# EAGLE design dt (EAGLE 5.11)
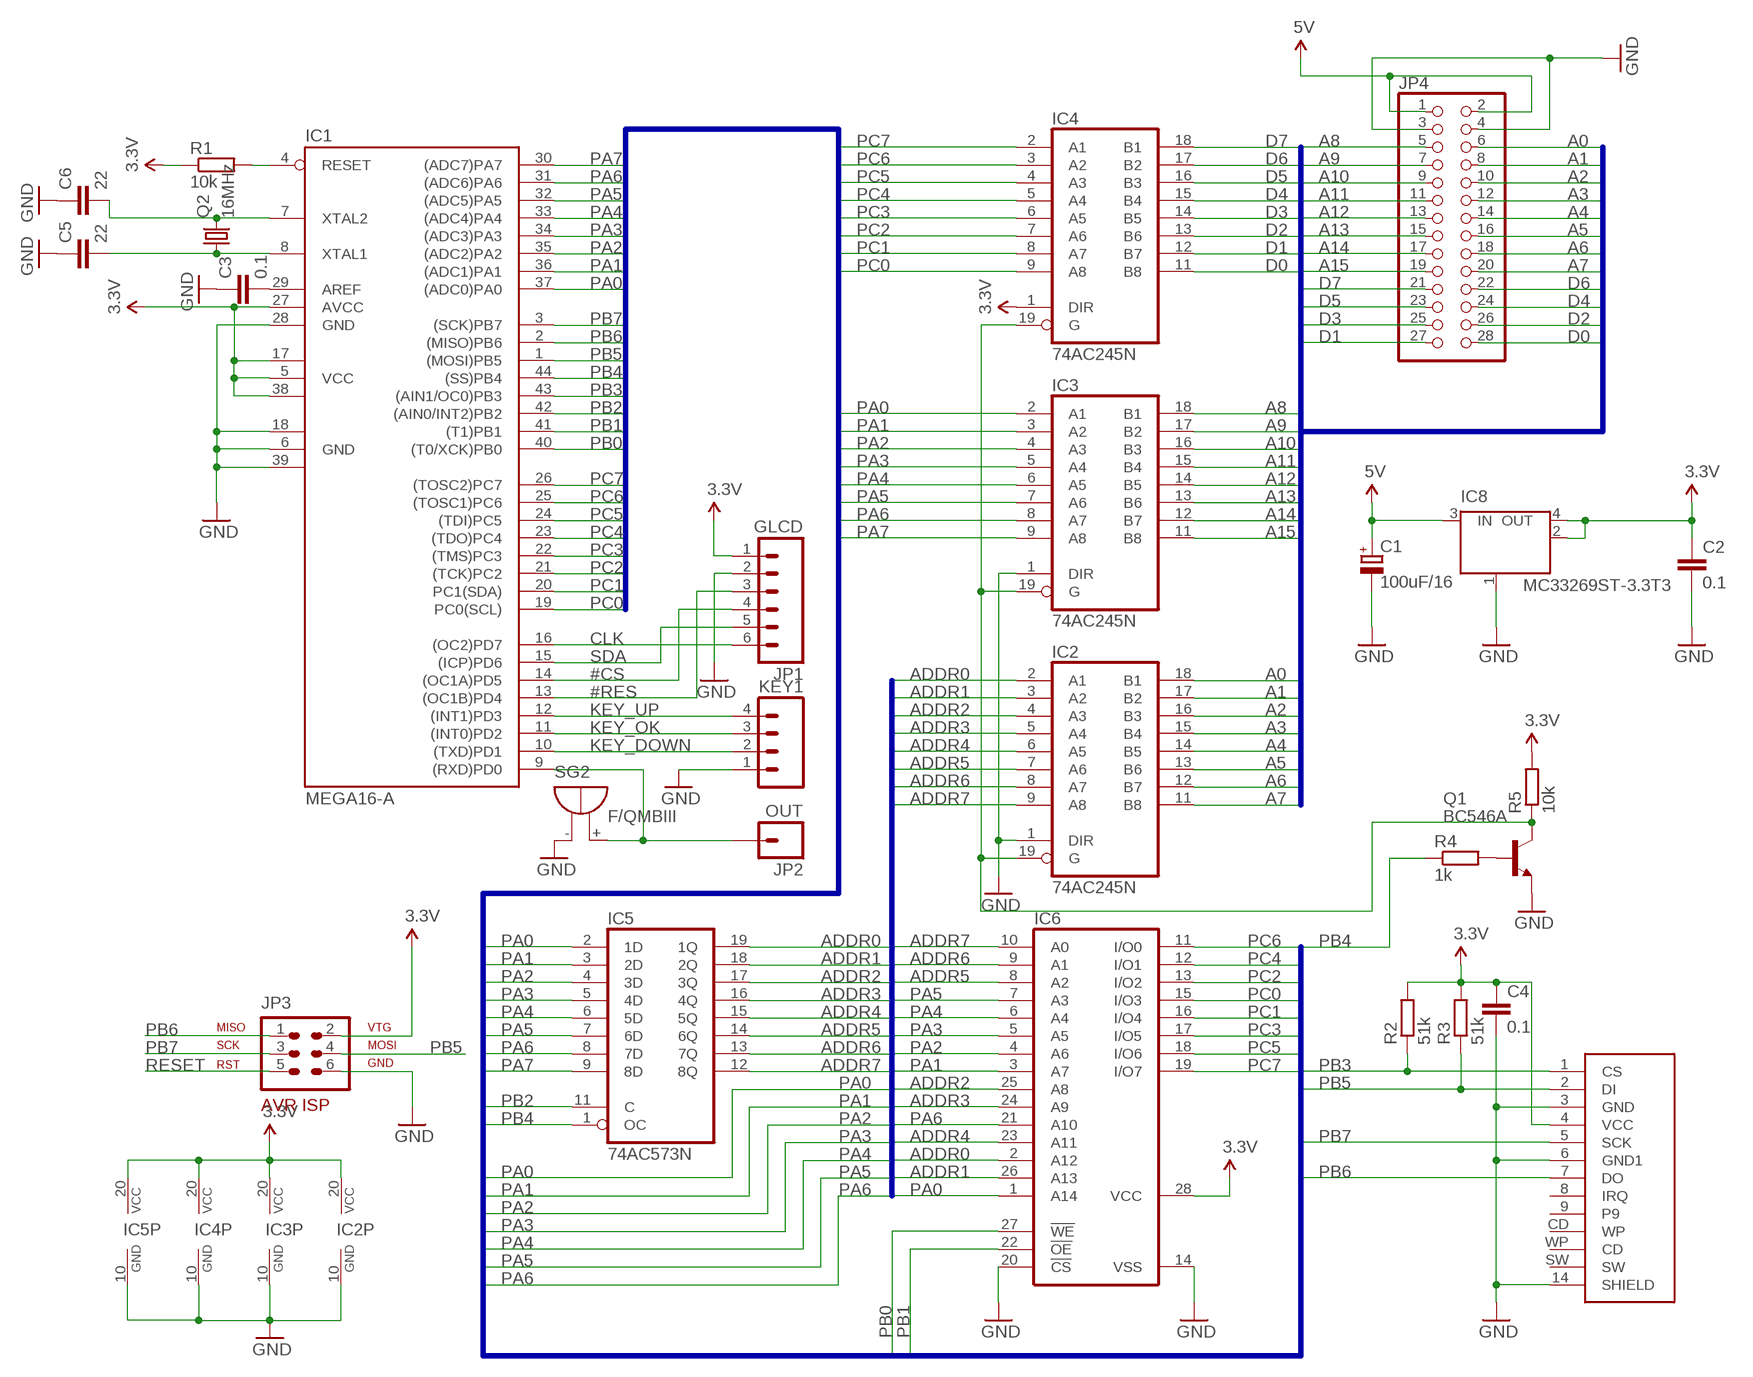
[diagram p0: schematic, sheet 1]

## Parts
C1  100uF/16  CPOL-EUE2,5-6E  [E2,5-6E]
C2  0.1  C-EU050-025X075  [C050-025X075]
C3  0.1  C-EU050-025X075  [C050-025X075]
C4  0.1  C-EU050-025X075  [C050-025X075]
C5  22  C-EU050-025X075  [C050-025X075]
C6  22  C-EU050-025X075  [C050-025X075]
IC1  MEGA16-A  [TQFP44]
IC2  74AC245N  [DIL20]
IC3  74AC245N  [DIL20]
IC4  74AC245N  [DIL20]
IC5  74AC573N  [DIL20]
IC6  62832P  [DIL28-3]
IC8  MC33269ST-3.3T3  [SOT223]
JP1  GLCD  M06POLAR  [MOLEX-1X6]
JP2  OUT  M01OFFSET  [1X01_OFFSET]
JP3  AVR-ISP-6  [AVR-ISP-6]
JP4  PINHD-2X14  [2X14]
KEY1  M04POLAR  [MOLEX-1X4]
Q1  BC546A  [TO92-EBC]
Q2  16MHz  CRYSTALHC49UP  [HC49UP]
R1  10k  R-EU_0207/10  [0207/10]
R2  51k  R-EU_0207/10  [0207/10]
R3  51k  R-EU_0207/10  [0207/10]
R4  1k  R-EU_0207/10  [0207/10]
R5  10k  R-EU_0207/10  [0207/10]
SG2  F/QMBIII  [F/QMBIII]
U$4  SD_CARD_SOCKETSD  [SD-MMC_SOCKET-PP]

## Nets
3.3V: C2.1 C4.1 IC1.5(VCC) IC1.17(VCC1) IC1.27(AVCC) IC1.38(VCC2) IC2.20(VCC) IC3.20(VCC) IC4.1(DIR) IC4.20(VCC) IC5.20(VCC) IC6.28(VCC) IC8.2(OUT) IC8.4(OUT) JP1.1 JP3.2 R1.1 R2.2 R3.2 R5.2 U$4.4(VCC)
5V: C1.+ IC8.3(IN) JP4.1 JP4.2
#CS: IC1.14((OC1A)PD5) JP1.4
#RES: IC1.13((OC1B)PD4) JP1.3
A0: IC2.18(B1) JP4.6
A1: IC2.17(B2) JP4.8
A2: IC2.16(B3) JP4.10
A3: IC2.15(B4) JP4.12
A4: IC2.14(B5) JP4.14
A5: IC2.13(B6) JP4.16
A6: IC2.12(B7) JP4.18
A7: IC2.11(B8) JP4.20
A8: IC3.18(B1) JP4.5
A9: IC3.17(B2) JP4.7
A10: IC3.16(B3) JP4.9
A11: IC3.15(B4) JP4.11
A12: IC3.14(B5) JP4.13
A13: IC3.13(B6) JP4.15
A14: IC3.12(B7) JP4.17
A15: IC3.11(B8) JP4.19
ADDR0: IC2.2(A1) IC5.19(1Q) IC6.2(A12)
ADDR1: IC2.3(A2) IC5.18(2Q) IC6.26(A13)
ADDR2: IC2.4(A3) IC5.17(3Q) IC6.25(A8)
ADDR3: IC2.5(A4) IC5.16(4Q) IC6.24(A9)
ADDR4: IC2.6(A5) IC5.15(5Q) IC6.23(A11)
ADDR5: IC2.7(A6) IC5.14(6Q) IC6.8(A2)
ADDR6: IC2.8(A7) IC5.13(7Q) IC6.9(A1)
ADDR7: IC2.9(A8) IC5.12(8Q) IC6.10(A0)
CLK: IC1.16((OC2)PD7) JP1.6
D0: IC4.11(B8) JP4.28
D1: IC4.12(B7) JP4.27
D2: IC4.13(B6) JP4.26
D3: IC4.14(B5) JP4.25
D4: IC4.15(B4) JP4.24
D5: IC4.16(B3) JP4.23
D6: IC4.17(B2) JP4.22
D7: IC4.18(B1) JP4.21
GND: C1.- C2.2 C3.1 C4.2 C5.1 C6.1 IC1.6(GND) IC1.18(GND1) IC1.28(GND) IC1.39(GND2) IC2.1(DIR) IC2.10(GND) IC3.1(DIR) IC3.10(GND) IC4.10(GND) IC5.10(GND) IC6.14(VSS) IC6.20(!CS) IC8.1(GND/ADJ) JP1.2 JP3.6 JP4.3 JP4.4 KEY1.1 Q1.E SG2.-(+) U$4.3(GND) U$4.6(GND1) U$4.14(SHIELD)
KEY_DOWN: IC1.10((TXD)PD1) KEY1.2
KEY_OK: IC1.11((INT0)PD2) KEY1.3
KEY_UP: IC1.12((INT1)PD3) KEY1.4
N$7: C3.2 IC1.29(AREF)
N$9: IC1.9((RXD)PD0) JP2.1 SG2.+(-)
N$10: Q1.B R4.2
N$11: IC2.19(G) IC3.19(G) IC4.19(G) Q1.C R5.1
N$13: C6.2 IC1.7(XTAL2) Q2.2
N$14: C5.2 IC1.8(XTAL1) Q2.1
PA0: IC1.37((ADC0)PA0) IC3.2(A1) IC5.2(1D) IC6.1(A14)
PA1: IC1.36((ADC1)PA1) IC3.3(A2) IC5.3(2D) IC6.3(A7)
PA2: IC1.35((ADC2)PA2) IC3.4(A3) IC5.4(3D) IC6.4(A6)
PA3: IC1.34((ADC3)PA3) IC3.5(A4) IC5.5(4D) IC6.5(A5)
PA4: IC1.33((ADC4)PA4) IC3.6(A5) IC5.6(5D) IC6.6(A4)
PA5: IC1.32((ADC5)PA5) IC3.7(A6) IC5.7(6D) IC6.7(A3)
PA6: IC1.31((ADC6)PA6) IC3.8(A7) IC5.8(7D) IC6.21(A10)
PA7: IC1.30((ADC7)PA7) IC3.9(A8) IC5.9(8D)
PB0: IC1.40((T0/XCK)PB0) IC6.27(!WE)
PB1: IC1.41((T1)PB1) IC6.22(!OE)
PB2: IC1.42((AIN0/INT2)PB2) IC5.11(C)
PB3: IC1.43((AIN1/OC0)PB3) R2.1 U$4.1(CS)
PB4: IC1.44((SS)PB4) IC5.1(OC) R4.1
PB5: IC1.1((MOSI)PB5) JP3.4 R3.1 U$4.2(DI)
PB6: IC1.2((MISO)PB6) JP3.1 U$4.7(DO)
PB7: IC1.3((SCK)PB7) JP3.3 U$4.5(SCK)
PC0: IC1.19(PC0(SCL)) IC4.9(A8) IC6.15(I/O3)
PC1: IC1.20(PC1(SDA)) IC4.8(A7) IC6.16(I/O4)
PC2: IC1.21((TCK)PC2) IC4.7(A6) IC6.13(I/O2)
PC3: IC1.22((TMS)PC3) IC4.6(A5) IC6.17(I/O5)
PC4: IC1.23((TDO)PC4) IC4.5(A4) IC6.12(I/O1)
PC5: IC1.24((TDI)PC5) IC4.4(A3) IC6.18(I/O6)
PC6: IC1.25((TOSC1)PC6) IC4.3(A2) IC6.11(I/O0)
PC7: IC1.26((TOSC2)PC7) IC4.2(A1) IC6.19(I/O7)
RESET: IC1.4(RESET) JP3.5 R1.2
SDA: IC1.15((ICP)PD6) JP1.5
Unconnected: U$4.8(IRQ) U$4.9 U$4.CD(WP) U$4.SW U$4.WP(CD)

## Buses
PA[0..7],PB[0..7],PC[0..7]
ADDR[0..14],PA[0..7]
A[0..15],D[0..7]

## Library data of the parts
C1 = rcl:CPOL-EU: POLARIZED CAPACITOR, European symbol
C2-C6 = rcl:C-EU: CAPACITOR, European symbol
IC1 = atmel:MEGA16: MICROCONTROLLER 16 Kbytes FLASH 1 kbytes SRAM 512 bytes EEPROM USART 8-channel 10 bit ADC Source: avr.lbr; MPN: ATMEGA16-16AU; OC_FARNELL: 9171134; OC_NEWARK: 96K6515
IC2-IC4 = 74xx-eu:74*245: Octal BUS TRANSCEIVER, 3-state
IC5 = 74xx-eu:74*573: 8-bit D latch BUS DRIVER
IC6 = memory-hitachi:62832P: MEMORY; OC_FARNELL: unknown; OC_NEWARK: unknown
IC8 = linear:MC33269ST*: Adjustable Output Low Dropout Voltage Regulator 800 mA Source: http://www.onsemi.com/pub/Collateral/MC33269-D.PDF
JP1 = SparkFun:M06: Header 6 Standard 6-pin 0.1" header. Use with straight break away headers (SKU : PRT-00116), right angle break away headers (PRT-00553), swiss pins (PRT-00743), machine pins (PRT-00117), and female headers (PRT-00115). Molex polarized connector foot print use with SKU : PRT-08094 with associated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
JP2 = SparkFun:M01: Header 1
JP3 = alex1:AVR-ISP-6: AVR ISP-6 Serial Programming Header
JP4 = pinhead:PINHD-2X14: PIN HEADER
KEY1 = SparkFun:M04: Header 4 Standard 4-pin 0.1" header. Use with straight break away headers (SKU : PRT-00116), right angle break away headers (PRT-00553), swiss pins (PRT-00743), machine pins (PRT-00117), and female headers (PRT-00115). Molex polarized connector foot print use with SKU : PRT-08231 with associated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
Q1 = transistor-npn:BC546*: NPN Transistor
Q2 = crystal:CRYSTAL: CRYSTAL; OC_FARNELL: unknown; OC_NEWARK: unknown
R1-R5 = rcl:R-EU_: RESISTOR, European symbol
SG2 = buzzer:F/QMBIII: BUZZER; OC_FARNELL: unknown; OC_NEWARK: unknown
U$4 = SparkFun:SD_CARD_SOCKET: SD/MMC Socket Media socket for SD and MMC cards. Push-push type. Schematic element and footprint production proven. Spark Fun Electronics SKU : PRT-00136

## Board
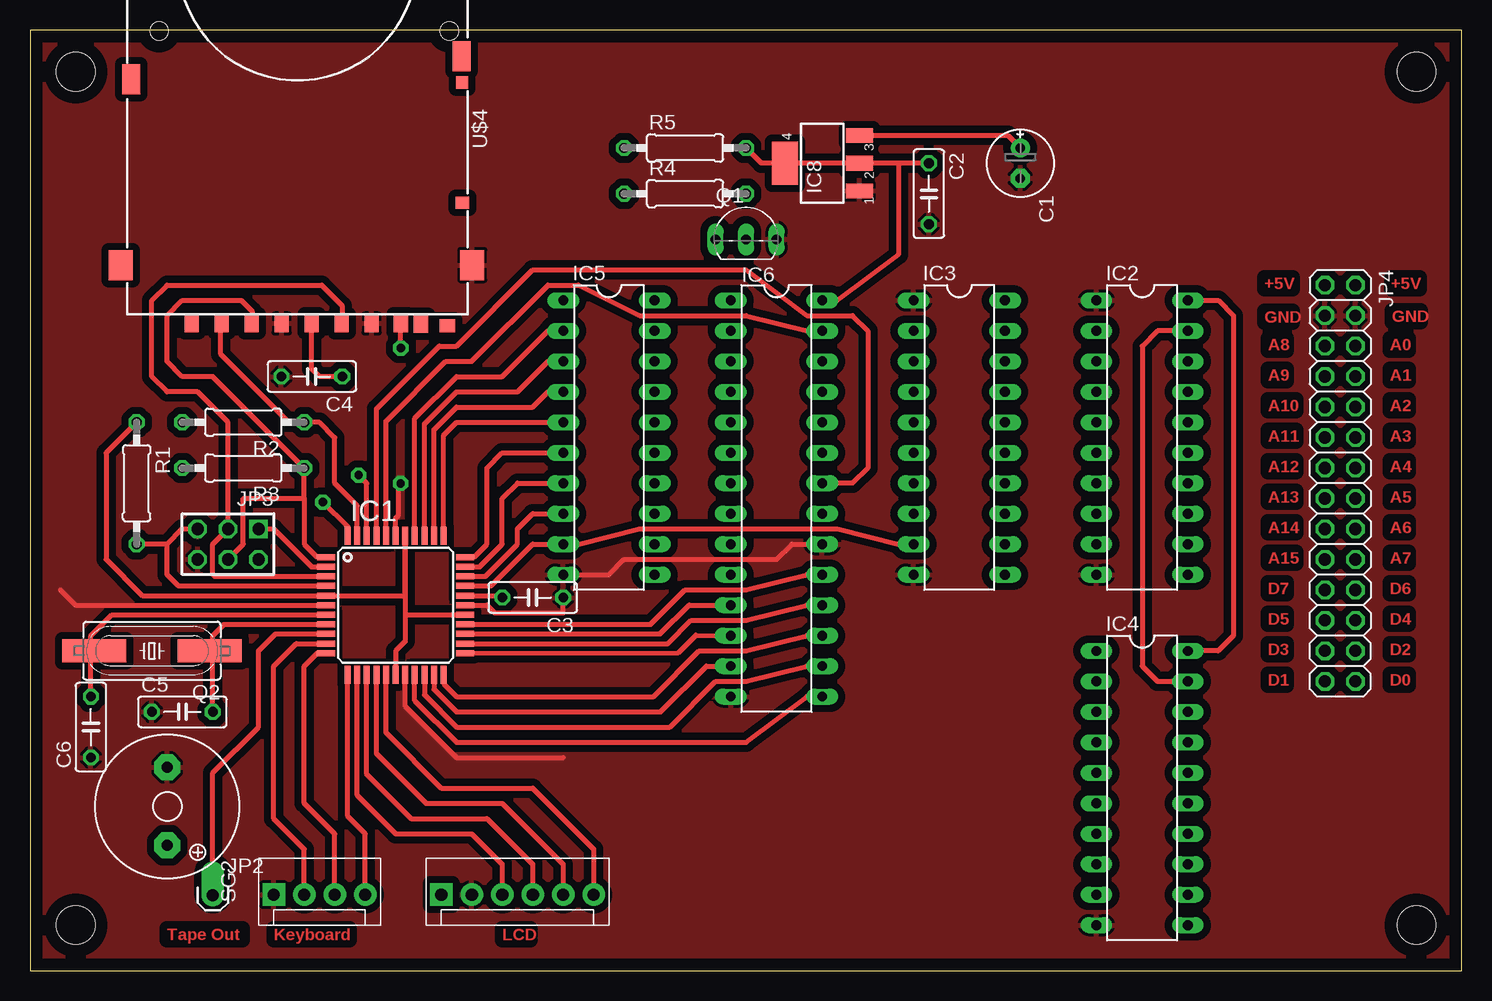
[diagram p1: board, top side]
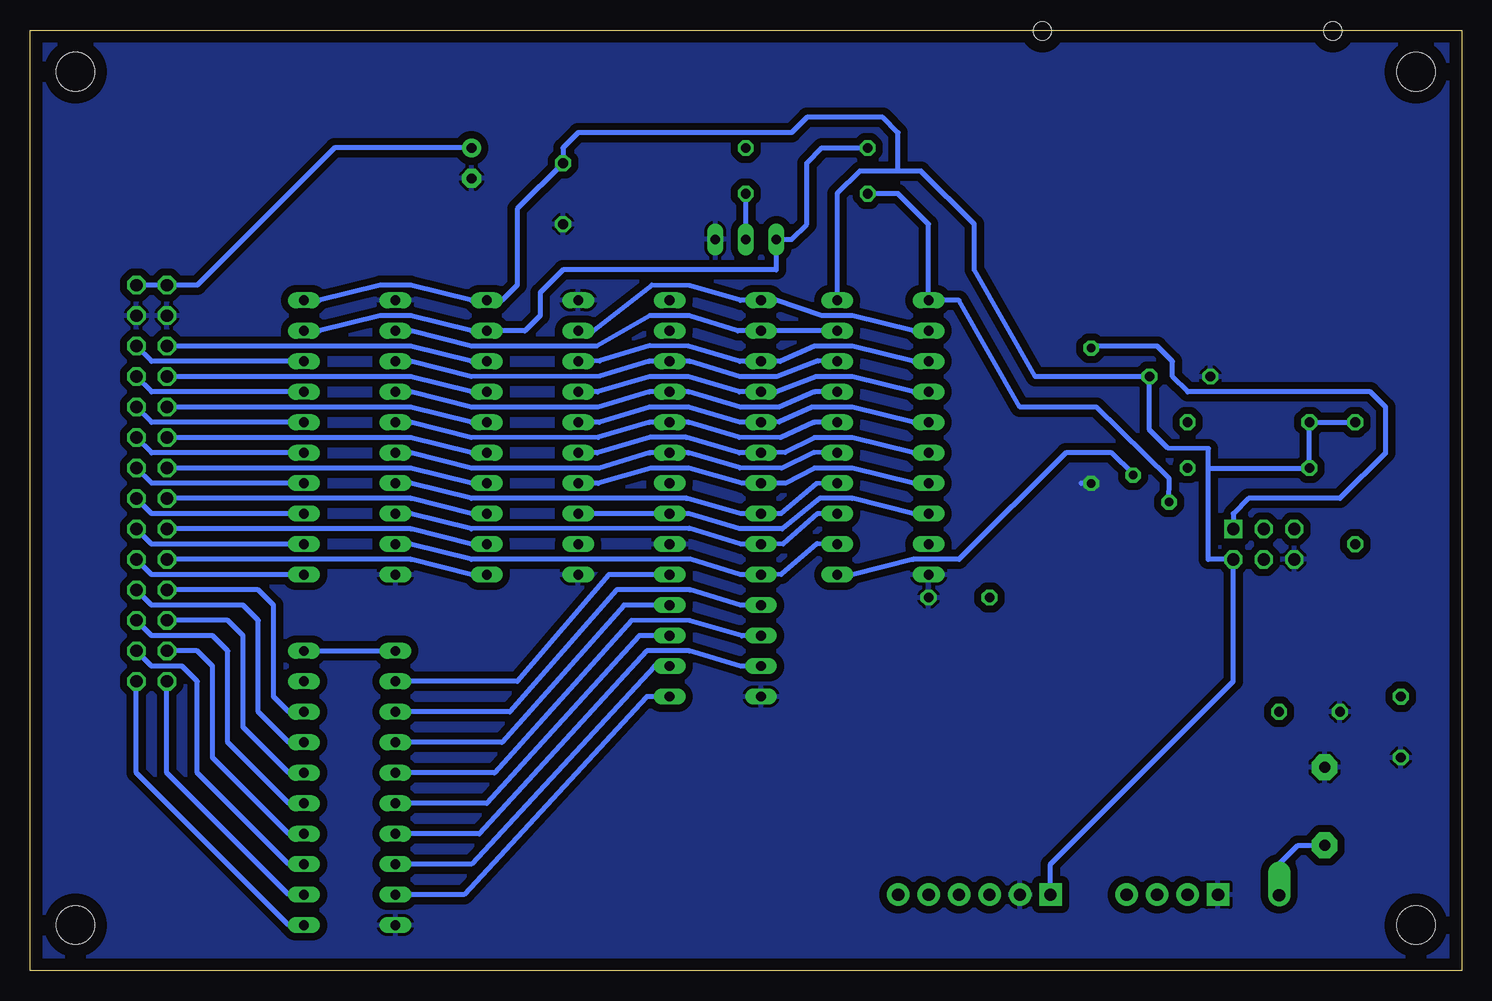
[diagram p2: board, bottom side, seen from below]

Size 119.36 x 78.41 mm. Coordinates in mm from the lower left corner, seen from the top.
Outline: 0,0 119.36,0 119.36,78.41 0,78.41 0,0
Copper layers (1*16): Top 0.035mm / dielectric 1.5mm / Bottom 0.035mm
Design rules "default": minimum track width 10mil, minimum drill 24mil, track to track 8mil, track to pad 8mil, pad to pad 8mil, via to via 8mil, smd to smd 8mil, copper to edge 40mil, drill to drill 8mil, minimum pad ring 10mil, minimum via ring 8mil, stop-mask expansion 4mil, vias tented up to drill 0mil, thermal gap 10mil
Holes 3.2 mm at 3.81,3.81 115.57,3.81 115.57,74.93 3.81,74.93

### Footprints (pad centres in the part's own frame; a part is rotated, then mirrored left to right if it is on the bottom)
E2,5-6E = drill 0.813 pad 1.575 round: + -1.27,0 | drill 0.813 pad 1.575 octagon: - 1.27,0
C050-025X075 = drill 0.813 octagon: 1 -2.54,0; 2 2.54,0
TQFP44 = smd 1.5 x 0.5: 1 -5.8,4; 2 -5.8,3.2; 3 -5.8,2.4; 4 -5.8,1.6; 5 -5.8,0.8; 6 -5.8,0; 7 -5.8,-0.8; 8 -5.8,-1.6; 9 -5.8,-2.4; 10 -5.8,-3.2; 11 -5.8,-4; 23 5.8,-4; 24 5.8,-3.2; 25 5.8,-2.4; 26 5.8,-1.6; 27 5.8,-0.8; 28 5.8,0; 29 5.8,0.8; 30 5.8,1.6; 31 5.8,2.4; 32 5.8,3.2; 33 5.8,4 | smd 0.5 x 1.5: 12 -4,-5.8; 13 -3.2,-5.8; 14 -2.4,-5.8; 15 -1.6,-5.8; 16 -0.8,-5.8; 17 0,-5.8; 18 0.8,-5.8; 19 1.6,-5.8; 20 2.4,-5.8; 21 3.2,-5.8; 22 4,-5.8; 34 4,5.8; 35 3.2,5.8; 36 2.4,5.8; 37 1.6,5.8; 38 0.8,5.8; 39 0,5.8; 40 -0.8,5.8; 41 -1.6,5.8; 42 -2.4,5.8; 43 -3.2,5.8; 44 -4,5.8
DIL20 = drill 0.813 long: 1 -11.43,-3.81; 2 -8.89,-3.81; 3 -6.35,-3.81; 4 -3.81,-3.81; 5 -1.27,-3.81; 6 1.27,-3.81; 7 3.81,-3.81; 8 6.35,-3.81; 9 8.89,-3.81; 10 11.43,-3.81; 11 11.43,3.81; 12 8.89,3.81; 13 6.35,3.81; 14 3.81,3.81; 15 1.27,3.81; 16 -1.27,3.81; 17 -3.81,3.81; 18 -6.35,3.81; 19 -8.89,3.81; 20 -11.43,3.81
DIL28-3 = drill 0.813 long: 1 -16.51,-3.81; 2 -13.97,-3.81; 3 -11.43,-3.81; 4 -8.89,-3.81; 5 -6.35,-3.81; 6 -3.81,-3.81; 7 -1.27,-3.81; 8 1.27,-3.81; 9 3.81,-3.81; 10 6.35,-3.81; 11 8.89,-3.81; 12 11.43,-3.81; 13 13.97,-3.81; 14 16.51,-3.81; 15 16.51,3.81; 16 13.97,3.81; 17 11.43,3.81; 18 8.89,3.81; 19 6.35,3.81; 20 3.81,3.81; 21 1.27,3.81; 22 -1.27,3.81; 23 -3.81,3.81; 24 -6.35,3.81; 25 -8.89,3.81; 26 -11.43,3.81; 27 -13.97,3.81; 28 -16.51,3.81
SOT223 = smd 1.219 x 2.235: 1 -2.311,-3.099; 2 0,-3.099; 3 2.311,-3.099 | smd 3.6 x 2.2: 4 0,3.099
MOLEX-1X6 = drill 1.016 pad 1.88 square: 1 0,0 | drill 1.016 pad 1.88 round: 2 2.54,0; 3 5.08,0; 4 7.62,0; 5 10.16,0; 6 12.7,0
1X01_OFFSET = drill 1.016 pad 1.88 offset: 1 0,0
AVR-ISP-6 = drill 1.016 square: 1 -2.54,-1.27 | drill 1.016 octagon: 2 -2.54,1.27; 3 0,-1.27; 4 0,1.27; 5 2.54,-1.27; 6 2.54,1.27
2X14 = drill 1.016 octagon: 1 -16.51,-1.27; 2 -16.51,1.27; 3 -13.97,-1.27; 4 -13.97,1.27; 5 -11.43,-1.27; 6 -11.43,1.27; 7 -8.89,-1.27; 8 -8.89,1.27; 9 -6.35,-1.27; 10 -6.35,1.27; 11 -3.81,-1.27; 12 -3.81,1.27; 13 -1.27,-1.27; 14 -1.27,1.27; 15 1.27,-1.27; 16 1.27,1.27; 17 3.81,-1.27; 18 3.81,1.27; 19 6.35,-1.27; 20 6.35,1.27; 21 8.89,-1.27; 22 8.89,1.27; 23 11.43,-1.27; 24 11.43,1.27; 25 13.97,-1.27; 26 13.97,1.27; 27 16.51,-1.27; 28 16.51,1.27
MOLEX-1X4 = drill 1.016 pad 1.88 square: 1 0,0 | drill 1.016 pad 1.88 round: 2 2.54,0; 3 5.08,0; 4 7.62,0
TO92-EBC = drill 0.813 long: B 0,-1.27; C -2.54,-1.27; E 2.54,-1.27
HC49UP = smd 5.334 x 1.93: 1 -4.826,0; 2 4.826,0
0207/10 = drill 0.813 octagon: 1 -5.08,0; 2 5.08,0
F/QMBIII = drill 0.914 pad 2.159 octagon: + 3.251,0; - -3.251,0
SD-MMC_SOCKET-PP = smd 1.2 x 1.5: 1 6.88,29.85; 2 4.38,29.85; 3 1.88,29.85; 4 -0.62,29.85; 5 -3.12,29.85; 6 -5.62,29.85; 7 -8.04,29.85; 8 -9.728,29.87; 9 9.38,29.85 | smd 1.5 x 2.5: 12 -13.1,7.6; 13 14.402,9.525 | smd 2 x 2.5: 14 -14,25; 15 15.3,25 | smd 1.15 x 1: CD -13.18,19.8 | smd 1.3 x 1.1: SW -11.938,30.048 | smd 1 x 1.05: WP -13.18,9.8 | hole 1.5: -12.1,5.5; 12.1,5.5

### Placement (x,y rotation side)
C1  82.55,67.31 270 top
C2  74.93,64.77 270 top
C3  41.91,31.11 180 top
C4  23.49,49.53 180 top
C5  12.7,21.59 0 top
C6  5.08,20.32 90 top
IC1  30.48,30.48 0 top
IC2  92.71,44.45 270 top
IC3  77.47,44.45 270 top
IC4  92.71,15.24 270 top
IC5  48.26,44.45 270 top
IC6  62.23,39.37 270 top
IC8  66.04,67.31 90 top
JP1  34.29,6.35 0 top
JP2  15.23,6.31 0 top
JP3  16.51,35.56 180 top
JP4  109.22,40.64 270 top
KEY1  20.32,6.35 0 top
Q1  59.69,62.23 0 top
Q2  10.16,26.67 180 top
R1  8.89,40.64 270 top
R2  17.78,45.72 180 top
R3  17.78,41.91 180 top
R4  54.61,64.77 0 top
R5  54.61,68.58 0 top
SG2  11.44,13.71 270 top
U$4  22.86,83.82 180 top

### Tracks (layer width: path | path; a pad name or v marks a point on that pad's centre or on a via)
3.3V
  Top 0.406: C2.1 72.39,67.31 | 72.39,67.31 IC8.2 IC8.4 60.96,67.31 R5.2 | IC2.20 99.06,55.88 100.33,54.61 100.33,27.94 99.06,26.67 IC4.20 | IC6.28 67.31,55.88 72.39,59.69 72.39,67.31 | 31.28,29.67 31.28,27.47 30.48,26.67 IC1.17 | 31.28,29.67 IC1.38 31.28,31.33 31.2,31.25 24.71,31.25 IC1.5 9.36,31.28 6.35,34.29 6.35,43.18 R1.1 | IC1.27 31.29,29.68 31.28,29.67 | U$4.4 23.48,50.18 24.13,49.53 C4.1
  Bottom 0.406: IC2.20 95.25,55.88 90.17,57.15 87.63,57.15 82.55,55.88 IC3.20 80.01,55.88 78.74,57.15 78.74,63.5 C2.1 74.93,68.58 73.66,69.85 55.88,69.85 54.61,71.12 48.26,71.12 46.99,69.85 46.99,66.64 | R1.1 R2.2 R3.2 21.14,41.91 | JP1.1 34.29,8.89 19.05,24.13 JP3.2 21.14,34.29 21.14,41.91 | 21.14,41.91 21.13,43.53 24.49,43.56 26.04,45.09 C4.1 35.56,49.53 40.64,58.42 40.64,62.23 45.07,66.64 46.99,66.64 | IC4.20 IC4.1 | IC5.20 52.07,64.77 50.18,66.65 46.99,66.64
5V
  Top 0.406: IC8.3 81.51,69.62 C1.+
  Bottom 0.406: JP4.2 JP4.1 105.41,57.15 93.98,68.58 C1.+
#CS
  Top 0.406: IC1.14 28.08,16.37 31.75,12.7 38.1,12.7 41.91,8.89 JP1.4
#RES
  Top 0.406: JP1.3 39.37,8.89 36.83,11.43 30.48,11.43 27.28,14.63 IC1.13
A0
  Bottom 0.406: IC2.18 109.22,50.8 JP4.6
A1
  Bottom 0.406: IC2.17 109.22,48.26 JP4.8
A2
  Bottom 0.406: IC2.16 109.22,45.72 JP4.10
A3
  Bottom 0.406: IC2.15 109.22,43.18 JP4.12
A4
  Bottom 0.406: IC2.14 109.22,40.64 JP4.14
A5
  Bottom 0.406: IC2.13 109.22,38.1 JP4.16
A6
  Bottom 0.406: IC2.12 109.22,35.56 JP4.18
A7
  Bottom 0.406: IC2.11 109.22,33.02 JP4.20
A8
  Bottom 0.406: IC3.18 82.55,50.8 87.63,52.07 JP4.5
A9
  Bottom 0.406: IC3.17 82.55,48.26 87.63,49.53 JP4.7
A10
  Bottom 0.406: IC3.16 82.55,45.72 87.63,46.99 JP4.9
A11
  Bottom 0.406: IC3.15 82.55,43.18 87.63,44.45 JP4.11
A12
  Bottom 0.406: IC3.14 82.55,40.64 87.63,41.91 JP4.13
A13
  Bottom 0.406: IC3.13 82.55,38.1 87.63,39.37 JP4.15
A14
  Bottom 0.406: IC3.12 82.55,35.56 87.63,36.83 JP4.17
A15
  Bottom 0.406: JP4.19 87.63,34.29 82.55,33.02 IC3.11
ADDR0
  Bottom 0.406: IC5.19 IC6.2 60.37,53.34 64.42,54.61 67.69,54.61 72.13,52.07 82.55,52.07 87.63,53.34 IC2.2
ADDR1
  Bottom 0.406: IC5.18 53.67,50.84 57.15,49.53 60.19,49.52 64.36,50.79 IC6.26 67.77,50.8 71.88,49.56 82.55,49.53 87.63,50.8 IC2.3
ADDR2
  Bottom 0.406: IC5.17 53.95,48.26 56.91,46.99 60.14,46.99 64.45,48.26 IC6.25 67.73,48.26 72.01,46.99 82.55,46.99 87.63,48.26 IC2.4
ADDR3
  Bottom 0.406: IC5.16 53.99,45.72 56.8,44.45 60.24,44.46 64.46,45.72 IC6.24 67.73,45.71 72,44.46 82.55,44.45 87.63,45.72 IC2.5
ADDR4
  Bottom 0.406: IC5.15 53.99,43.21 56.72,41.91 60.18,41.92 64.48,43.17 IC6.23 67.71,43.18 71.91,41.91 82.55,41.91 87.63,43.18 IC2.6
ADDR5
  Bottom 0.406: IC5.14 53.81,40.61 56.75,38.1 IC6.8 60.13,38.1 64.65,39.37 82.55,39.37 87.63,40.64 IC2.7
ADDR6
  Bottom 0.406: IC5.13 53.71,38.1 56.55,35.59 IC6.9 60.09,35.56 64.44,36.87 82.55,36.83 87.63,38.1 IC2.8
ADDR7
  Bottom 0.406: IC5.12 53.74,35.6 56.73,33.05 IC6.10 60.14,33.02 64.31,34.31 82.55,34.29 87.63,35.56 IC2.9
CLK
  Top 0.406: IC1.16 29.68,19.85 34.29,15.24 41.91,15.24 46.99,10.16 JP1.6
D0
  Bottom 0.406: IC4.11 97.79,3.81 110.49,16.51 JP4.28
D1
  Bottom 0.406: IC4.12 97.79,6.35 107.95,16.51 JP4.27
D2
  Bottom 0.406: IC4.13 97.79,8.89 105.41,16.51 105.41,24.13 106.68,25.4 109.22,25.4 JP4.26
D3
  Bottom 0.406: IC4.14 97.79,11.43 104.14,17.78 104.14,25.4 105.41,26.67 JP4.25
D4
  Bottom 0.406: IC4.15 97.79,13.97 102.87,19.05 102.87,26.67 104.14,27.94 109.22,27.94 JP4.24
D5
  Bottom 0.406: IC4.16 97.79,16.51 101.6,20.32 101.6,27.94 102.87,29.21 JP4.23
D6
  Bottom 0.406: IC4.17 97.79,19.05 100.33,21.59 100.33,29.21 101.6,30.48 109.22,30.48 JP4.22
D7
  Bottom 0.406: IC4.18 97.79,21.59 99.06,22.86 99.06,30.48 100.33,31.75 JP4.21
GND  (via drill 0.7 pad 1.27)
  Top 0.406: IC1.28 38.1,30.48 38.73,29.84 44.45,29.84 C3.1 | IC1.18 31.28,22.06 35.56,17.78 44.45,17.78 | IC1.39 30.48,37.73 30.71,37.96 30.71,40.44 v30.9,40.63 | IC1.6 3.81,30.48 2.54,31.75 | IC5.10 48.26,33.02 49.53,34.29 62.23,34.29 63.5,35.56 IC6.20
  Bottom 0.406: v30.9,40.63 31.74,40.63 31.75,40.64
  pour Top (isolate 0.61): 0,78.74 119.38,78.74 119.38,0 0,0
  pour Bottom (isolate 0.61): 0,78.74 119.38,78.74 119.38,0 0,0
KEY_DOWN
  Top 0.406: IC1.10 22.2,27.28 20.32,25.4 20.32,12.7 22.86,10.16 KEY1.2
KEY_OK
  Top 0.406: IC1.11 23.94,26.48 22.86,25.4 22.86,13.97 25.4,11.43 KEY1.3
KEY_UP
  Top 0.406: IC1.12 26.48,12.89 27.94,11.43 KEY1.4
N$7
  Top 0.406: IC1.29 39.2,31.28 C3.2
N$9
  Top 0.406: IC1.9 20.46,28.08 19.05,26.67 19.05,20.32 15.24,16.51 JP2.1
  Bottom 0.406: SG2.+ 13.67,10.46 15.24,8.89 JP2.1
N$10
  Bottom 0.406: Q1.B R4.2
N$11
  Top 0.406: IC4.19 93.98,24.13 92.71,25.4 92.71,52.07 93.98,53.34 IC2.19
  Bottom 0.406: IC2.19 95.25,53.34 90.17,54.61 87.63,54.61 82.55,53.34 IC3.19 78.11,53.34 76.84,54.61 76.84,56.52 74.93,58.42 57.15,58.42 Q1.C 55.88,60.96 54.61,62.23 54.61,67.31 53.34,68.58 R5.1
N$13
  Top 0.406: IC1.7 6.82,29.68 5.08,27.94 5.08,26.92 Q2.2 5.08,26.42 C6.2
N$14
  Top 0.406: IC1.8 16.18,28.88 15.24,27.94 15.24,26.92 Q2.1 15.24,26.42 C5.2
PA0
  Top 0.406: IC1.37 32.08,46.05 35.56,49.53 39.37,49.53 43.18,53.34 IC5.2
  Bottom 0.406: IC5.2 45.72,53.34 50.8,54.61 53.34,54.61 57.15,55.88 IC6.1 60.14,55.88 64.34,57.11 67.51,57.15 72.39,53.34 IC3.2
PA1
  Top 0.406: IC1.36 32.88,45.58 35.56,48.26 40.64,48.26 43.18,50.8 IC5.3
  Bottom 0.406: IC5.3 45.72,50.8 50.8,52.07 53.98,52.07 56.8,50.8 IC6.3 | IC6.3 59.69,50.8 | IC6.3 60.2,50.8 64.48,52.07 67.7,52.1 71.88,50.83 IC3.3
PA2
  Top 0.406: IC1.35 33.68,45.11 35.56,46.99 41.91,46.99 43.18,48.26 IC5.4
  Bottom 0.406: IC5.4 45.72,48.26 50.8,49.53 53.84,49.53 57.15,48.26 IC6.4 60.23,48.26 64.48,49.53 67.7,49.53 72.03,48.26 IC3.4
PA3
  Top 0.406: IC1.34 34.48,44.64 35.56,45.72 IC5.5
  Bottom 0.406: IC5.5 45.72,45.72 50.8,46.99 54.19,46.99 56.88,45.76 IC6.5 60.21,45.73 64.45,46.99 67.72,46.99 71.9,45.72 IC3.5
PA4
  Top 0.406: IC1.33 37.02,34.48 38.1,35.56 38.1,41.91 39.37,43.18 IC5.6
  Bottom 0.406: IC5.6 45.72,43.18 50.8,44.45 53.98,44.45 56.41,43.22 IC6.6 60.24,43.18 64.66,44.47 67.64,44.48 72.05,43.18 IC3.6
PA5
  Top 0.406: IC1.32 37.49,33.68 39.37,35.56 39.37,39.37 40.64,40.64 IC5.7
  Bottom 0.406: IC5.7 45.72,40.64 50.8,41.91 53.98,41.91 56.38,40.64 IC6.7 60.01,40.64 64.44,41.91 67.6,41.91 72,40.63 IC3.7
PA6
  Top 0.406: IC1.31 37.96,32.88 40.64,35.56 40.64,36.83 41.91,38.1 IC5.8
  Bottom 0.406: IC5.8 45.72,38.1 50.8,39.37 53.49,39.4 56.63,36.83 60.23,36.85 64.44,38.11 IC6.21 IC3.8
PA7
  Top 0.406: IC1.30 38.43,32.08 41.91,35.56 IC5.9 45.72,35.56 50.8,36.83 67.31,36.83 72.39,35.56 IC3.9
PB0
  Top 0.406: IC6.27 64.77,53.34 59.69,54.61 50.8,54.61 45.72,57.15 43.18,57.15 36.83,50.8 34.65,50.8 29.67,45.82 IC1.40
PB1
  Top 0.406: IC6.22 68.58,40.64 69.85,41.91 69.85,53.34 68.58,54.61 64.77,54.61 59.69,58.42 41.91,58.42 35.56,52.07 34.11,52.07 28.88,46.84 IC1.41
PB2  (via drill 0.7 pad 1.27)
  Top 0.406: IC1.42 28.08,40.63 v27.4,41.31
  Bottom 0.406: IC5.11 50.8,33.02 45.72,34.29 41.91,34.29 33.02,43.18 29.21,43.18 27.4,41.37 v27.4,41.31
PB3
  Top 0.406: U$4.1 15.9,53.89 15.9,51.4 21.58,45.72 R2.1 24.13,45.72 25.4,44.45 25.4,40.64 27.28,38.76 IC1.43
PB4  (via drill 0.7 pad 1.27)
  Top 0.406: IC1.44 26.48,37.02 v24.41,39.06
  Bottom 0.406: R4.1 46.99,64.77 44.45,62.23 IC5.1 41.91,55.88 36.83,46.99 30.48,46.99 24.4,41.02 v24.41,39.06
PB5
  Top 0.406: IC1.1 23.94,34.48 22.86,35.56 22.86,39.37 | 22.86,39.37 R3.1 15.24,49.53 12.7,49.53 11.43,50.8 11.43,54.61 12.7,55.88 17.61,55.88 18.5,54.99 18.5,53.99 U$4.2 | JP3.4 17.78,35.56 17.78,39.37 22.86,39.37
PB6  (via drill 0.7 pad 1.27)
  Top 0.406: v30.91,51.9 U$4.7 | IC1.2 23.47,33.68 20.32,36.83 JP3.1
  Bottom 0.406: JP3.1 19.05,38.1 17.78,39.37 10.16,39.37 6.35,43.18 6.35,46.99 7.62,48.26 22.86,48.26 24.13,49.53 24.13,50.8 25.4,52.07 30.74,52.07 v30.91,51.9
PB7
  Top 0.406: IC1.3 15.38,32.88 15.24,33.02 15.24,35.56 JP3.3 16.51,45.72 13.97,48.26 11.43,48.26 10.16,49.53 10.16,55.88 11.43,57.15 24.32,57.15 26.02,55.45 26.02,54.01 U$4.5
PC0
  Top 0.406: IC1.19 32.08,22.53 35.56,19.05 59.69,19.05 64.77,22.86 IC6.15
  Bottom 0.406: IC6.15 67.95,22.86 83.19,6.35 IC4.9
PC1
  Top 0.406: IC1.20 32.88,23 35.56,20.32 53.34,20.32 57.15,24.13 59.69,24.13 64.77,25.4 IC6.16
  Bottom 0.406: IC6.16 67.31,25.4 82.55,8.89 IC4.8
PC2
  Top 0.406: IC1.21 33.68,23.47 35.56,21.59 52.57,21.59 56.38,25.4 IC6.13
  Bottom 0.406: IC6.13 60.11,25.4 64.42,26.67 67.95,26.67 81.92,11.43 IC4.7
PC3
  Top 0.406: IC1.22 34.48,23.94 35.56,22.86 51.98,22.86 55.79,26.67 59.69,26.67 64.77,27.94 IC6.17
  Bottom 0.406: IC6.17 68.58,27.94 81.28,13.97 IC4.6
PC4
  Top 0.406: IC1.23 54.06,26.52 55.52,27.98 IC6.12
  Bottom 0.406: IC6.12 60.02,27.93 64.36,29.2 69.22,29.21 80.65,16.51 IC4.5
PC5
  Top 0.406: IC1.24 53.19,27.28 55.12,29.21 59.69,29.21 64.77,30.48 IC6.18
  Bottom 0.406: IC6.18 69.85,30.48 80.01,19.05 IC4.4
PC6
  Top 0.406: IC1.25 52.54,28.08 54.94,30.48 IC6.11
  Bottom 0.406: IC6.11 60.14,30.49 64.34,31.75 70.48,31.75 79.38,21.59 IC4.3
PC7
  Top 0.406: IC1.26 51.74,28.88 54.61,31.75 59.69,31.75 64.77,33.02 IC6.19
  Bottom 0.406: IC6.19 71.12,33.02 78.74,24.13 IC4.2
RESET
  Top 0.406: 11.43,35.56 R1.2 | 11.43,35.56 12.7,36.83 JP3.5 13.97,36.2 | IC1.4 12.37,32.08 11.43,33.02 11.43,35.56
SDA
  Top 0.406: IC1.15 28.88,18.11 33.02,13.97 39.37,13.97 44.45,8.89 JP1.5

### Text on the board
Top: +5V | +5V | GND | GND | A8 | A0 | A9 | A1 | A10 | A2 | A11 | A3 | A12 | A4 | A13 | A5 | A14 | A6 | A15 | A7 | D7 | D6 | D5 | D4 | D3 | D2 | D1 | D0 | Tape Out | Keyboard | LCD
